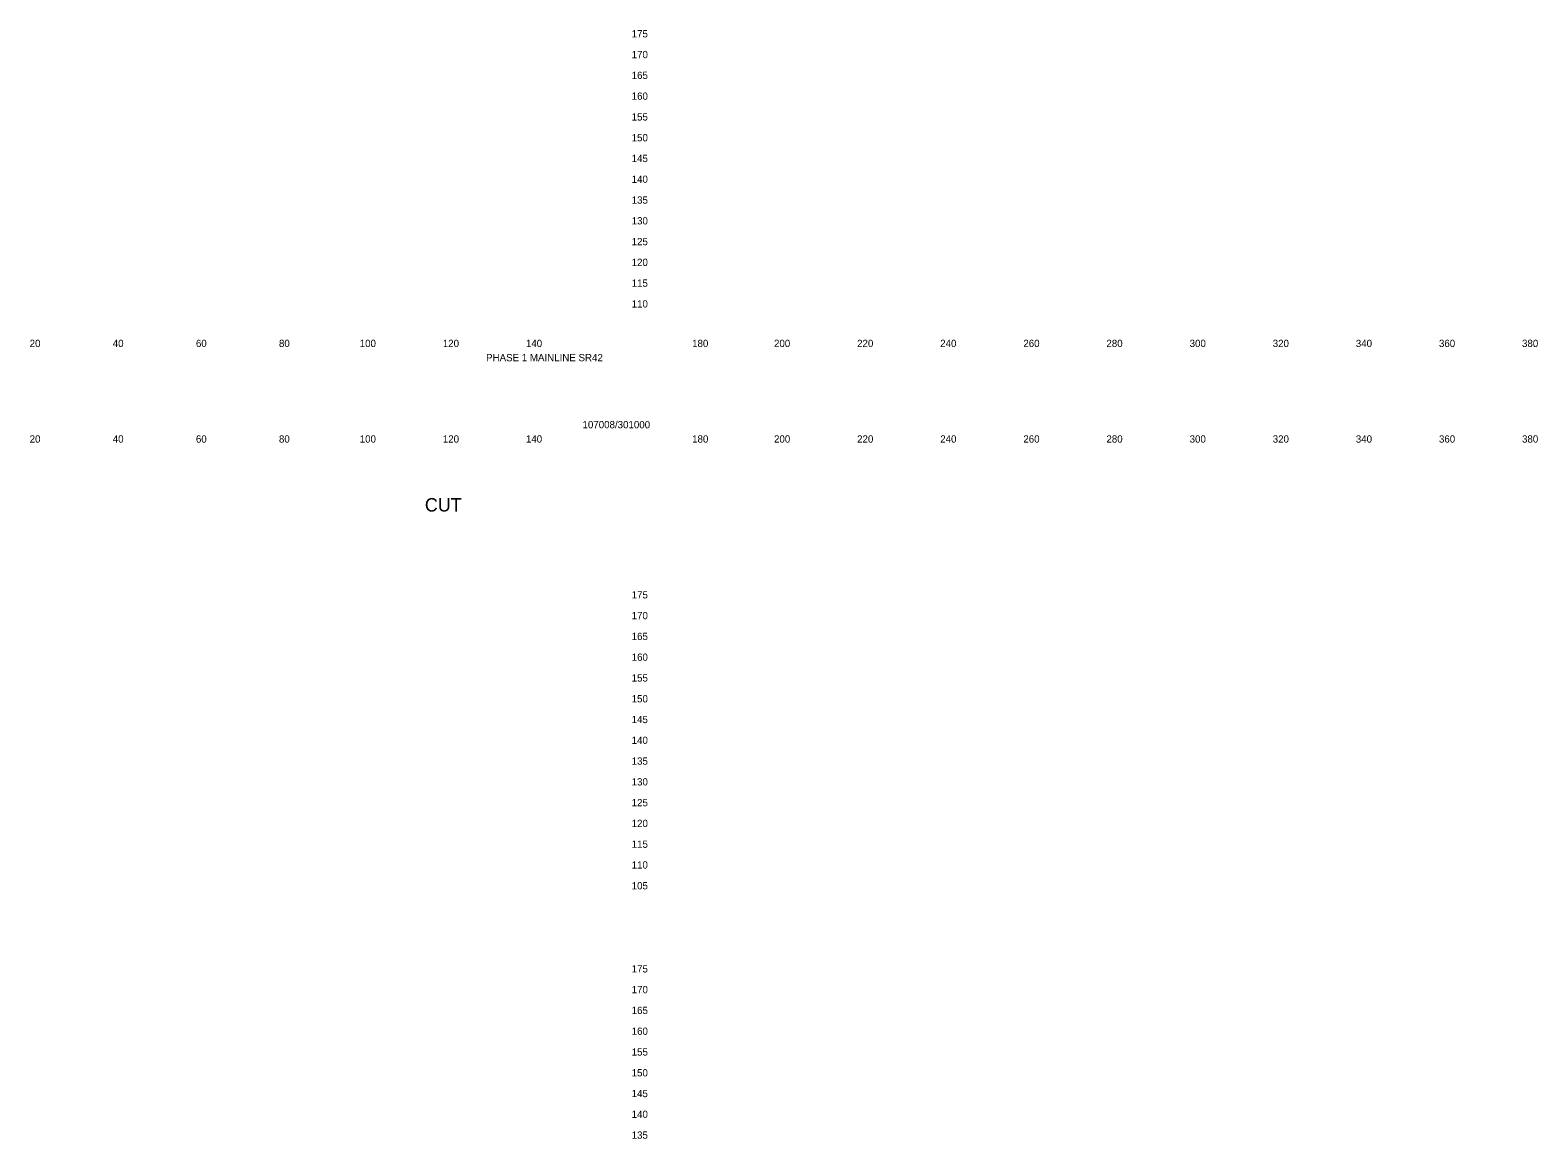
# Model space of a CAD drawing. Extents: x 21281 to 22024, y 6472 to 15198.
# Drawn here: x 21661.4 to 22024.2, y 11114.8 to 11381.6 of the extents above; entities that cross this region are included whole.
import ezdxf

# ---------------------------------------------------------------- set-up
doc = ezdxf.new("R2010")
doc.units = 0
doc.layers.add('XS_SHEET_LABELS_ELEVATION', color=7, linetype='Continuous')
doc.layers.add('XS_SHEET_LABELS_OFFSET', color=7, linetype='Continuous')

msp = doc.modelspace()

# ---------------------------------------------------------------- texts
at = {"layer": 'XS_SHEET_LABELS_ELEVATION'}
for s, p in [('  175  ', (21804.84, 11379.84)), ('  170  ', (21804.84, 11374.84)), ('  165  ', (21804.84, 11369.84)), ('  160  ', (21804.84, 11364.84)), ('  155  ', (21804.84, 11359.84)), ('  150  ', (21804.84, 11354.84)), ('  145  ', (21804.84, 11349.84)), ('  140  ', (21804.84, 11344.84)), ('  135  ', (21804.84, 11339.84)), ('  130  ', (21804.84, 11334.84)), ('  125  ', (21804.84, 11329.84)), ('  120  ', (21804.84, 11324.84)), ('  115  ', (21804.84, 11319.84)), ('  110  ', (21804.84, 11314.84)), ('  175  ', (21804.84, 11244.84)), ('  170  ', (21804.84, 11239.84)), ('  165  ', (21804.84, 11234.84)), ('  160  ', (21804.84, 11229.84)), ('  155  ', (21804.84, 11224.84)), ('  150  ', (21804.84, 11219.84)), ('  145  ', (21804.84, 11214.84)), ('  140  ', (21804.84, 11209.84)), ('  135  ', (21804.84, 11204.84)), ('  130  ', (21804.84, 11199.84)), ('  125  ', (21804.84, 11194.84)), ('  120  ', (21804.84, 11189.84)), ('  115  ', (21804.84, 11184.84)), ('  110  ', (21804.84, 11179.84)), ('  105  ', (21804.84, 11174.84)), ('  175  ', (21804.84, 11154.84)), ('  170  ', (21804.84, 11149.84)), ('  165  ', (21804.84, 11144.84)), ('  160  ', (21804.84, 11139.84)), ('  155  ', (21804.84, 11134.84)), ('  150  ', (21804.84, 11129.84)), ('  145  ', (21804.84, 11124.84)), ('  140  ', (21804.84, 11119.84)), ('  135  ', (21804.84, 11114.84))]:
    msp.add_text(s, height=1.75, dxfattribs=at).set_placement(p)
at = {"layer": 'XS_SHEET_LABELS_OFFSET'}
for s, height, p in [('  20  ', 1.75, (21659.95, 11305.34)), ('  40  ', 1.75, (21679.95, 11305.34)), ('  60  ', 1.75, (21699.97, 11305.34)), ('  80  ', 1.75, (21719.95, 11305.34)), ('  100  ', 1.75, (21739.39, 11305.34)), ('  120  ', 1.75, (21759.39, 11305.34)), ('  140  ', 1.75, (21779.39, 11305.34)), ('  180  ', 1.75, (21819.39, 11305.34)), ('  200  ', 1.75, (21839.1, 11305.34)), ('  220  ', 1.75, (21859.1, 11305.34)), ('  240  ', 1.75, (21879.1, 11305.34)), ('  260  ', 1.75, (21899.11, 11305.34)), ('  280  ', 1.75, (21919.1, 11305.34)), ('  300  ', 1.75, (21939.13, 11305.34)), ('  320  ', 1.75, (21959.13, 11305.34)), ('  340  ', 1.75, (21979.13, 11305.34)), ('  360  ', 1.75, (21999.14, 11305.34)), ('  380  ', 1.75, (22019.13, 11305.34)), ('PHASE 1 MAINLINE SR42', 1.75, (21771.11, 11301.92)), ('107008/301000', 1.75, (21794.31, 11285.79)), ('  20  ', 1.75, (21659.95, 11282.34)), ('  40  ', 1.75, (21679.95, 11282.34)), ('  60  ', 1.75, (21699.97, 11282.34)), ('  80  ', 1.75, (21719.95, 11282.34)), ('  100  ', 1.75, (21739.39, 11282.34)), ('  120  ', 1.75, (21759.39, 11282.34)), ('  140  ', 1.75, (21779.39, 11282.34)), ('  180  ', 1.75, (21819.39, 11282.34)), ('  200  ', 1.75, (21839.1, 11282.34)), ('  220  ', 1.75, (21859.1, 11282.34)), ('  240  ', 1.75, (21879.1, 11282.34)), ('  260  ', 1.75, (21899.11, 11282.34)), ('  280  ', 1.75, (21919.1, 11282.34)), ('  300  ', 1.75, (21939.13, 11282.34)), ('  320  ', 1.75, (21959.13, 11282.34)), ('  340  ', 1.75, (21979.13, 11282.34)), ('  360  ', 1.75, (21999.14, 11282.34)), ('  380  ', 1.75, (22019.13, 11282.34)), ('CUT', 3.222, (21756.37, 11265.76))]:
    msp.add_text(s, height=height, dxfattribs=at).set_placement(p)

doc.saveas('drawing.dxf')
